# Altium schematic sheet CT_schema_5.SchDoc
size 218 x 258 mm
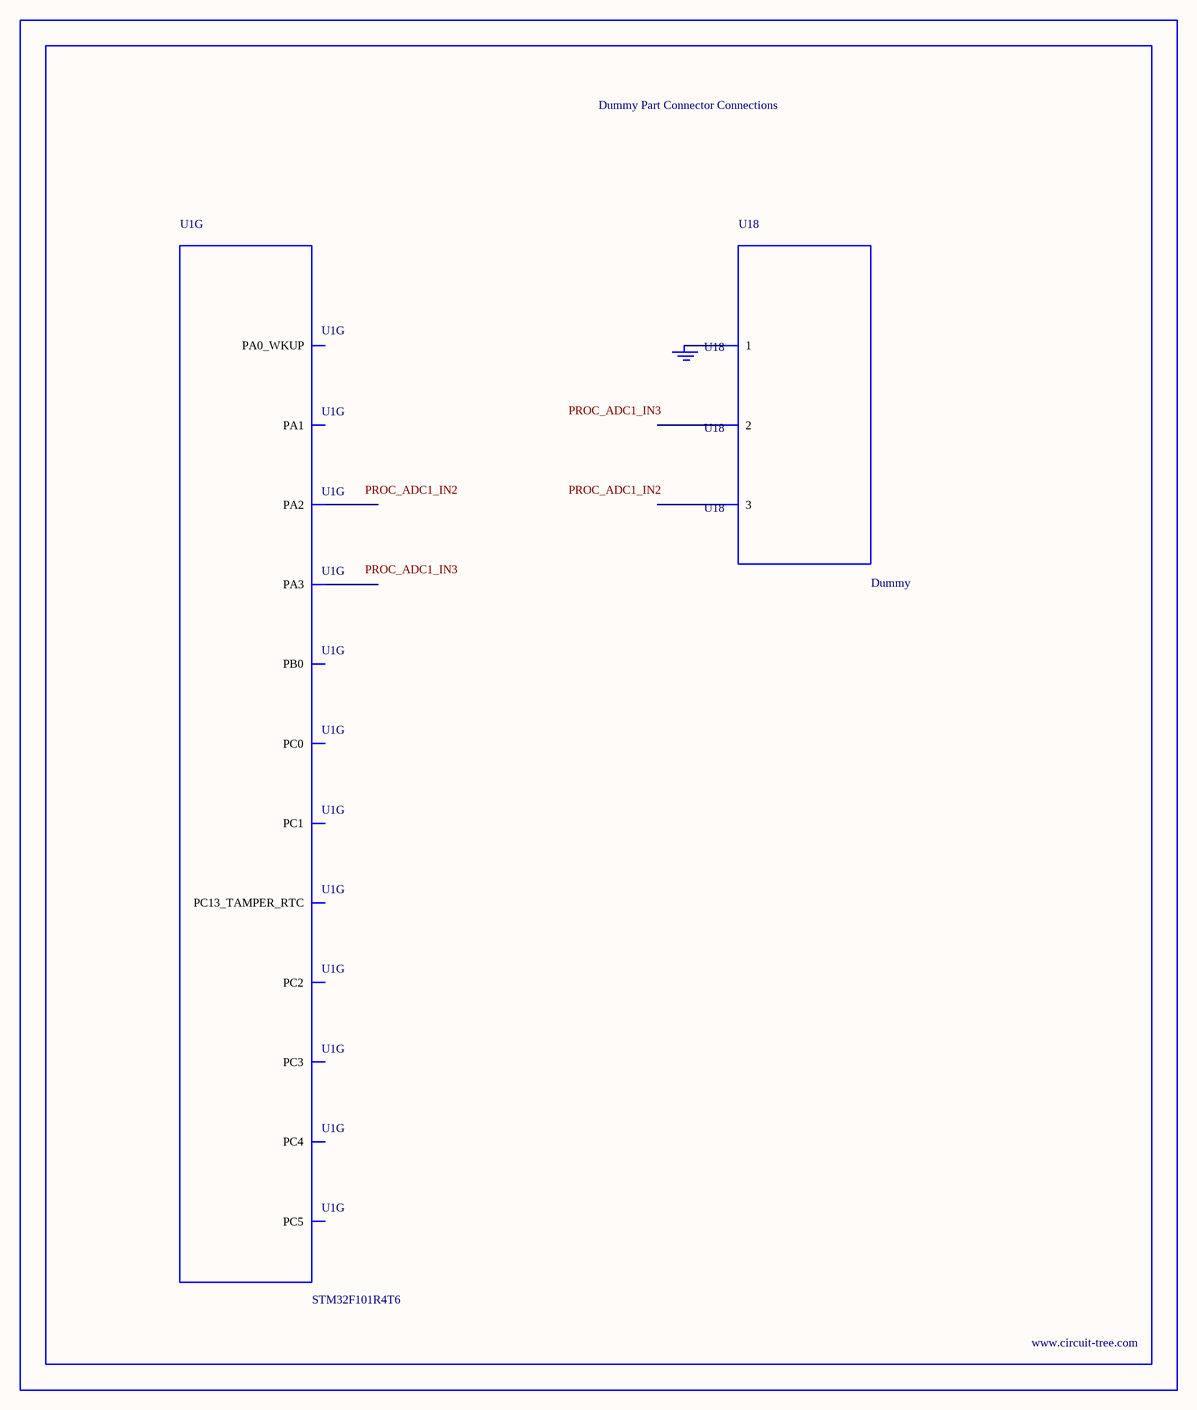
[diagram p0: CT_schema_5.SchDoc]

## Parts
BORDER4  (no value)
GND_INSTANCE_4_0  (no value)
U1  STM32F101R4T6  [LQFP64]  (part G of 7)
U18  Dummy  [DUMMY_PACKAGE_154]

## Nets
NetGND_INSTANCE_4_0_0: GND_INSTANCE_4_0.0(GND) U18.1

Not connected (* = marked no-connect by the designer): U1 2(PC13_TAMPER_RTC) 8(PC0) 9(PC1) 10(PC2) 11(PC3) 14(PA0_WKUP) 15(PA1) 16(PA2) 17(PA3) 24(PC4) 25(PC5) 26(PB0); U18 2 3

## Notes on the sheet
- Labels drawn without touching a wire or pin: PROC_ADC1_IN2, PROC_ADC1_IN3

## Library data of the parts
BORDER4 = BORDER_PAGE4
GND_INSTANCE_4_0 = GND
